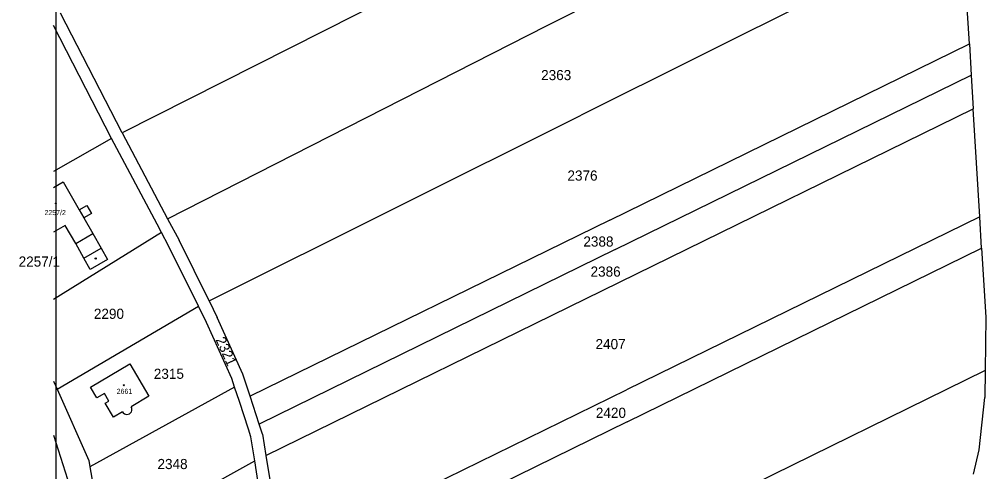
# Model space of a CAD drawing. Extents: x -565355 to -564154, y -1097649 to -1095548.
# Drawn here: x -565355.1 to -565030.7, y -1097072.9 to -1096921.2 of the extents above; entities that cross this region are included whole.
import ezdxf

# ---------------------------------------------------------------- set-up
doc = ezdxf.new("R2010")
doc.units = 0
for name, color, linetype in [('Vrstva 1', 7, 'Continuous'), ('Vrstva 18', 7, 'Continuous'), ('Vrstva 19', 7, 'Continuous'), ('Vrstva 25', 7, 'Continuous'), ('Vrstva 4', 7, 'Continuous'), ('Vrstva 63', 7, 'Continuous')]:
    doc.layers.add(name, color=color, linetype=linetype)

msp = doc.modelspace()

# ---------------------------------------------------------------- linework, layer by layer
at = {"layer": 'Vrstva 1'}
for p, q in [((-565178.1, -1096923.38), (-565050.85, -1096858.7)), ((-565191.34, -1096893.95), (-565320.5, -1096959.27)), ((-565041.65, -1096891.05), (-565166.5, -1096953.32)), ((-565036.11, -1096929.37), (-565037.8, -1096901.06)), ((-565320.5, -1096959.27), (-565341.23, -1096919.07)), ((-565324.11, -1096961.15), (-565343.59, -1096923.24)), ((-565305.34, -1096988.06), (-565178.1, -1096923.38)), ((-565156.86, -1096988.48), (-565036.11, -1096929.37)), ((-565036.11, -1096929.37), (-565035.5, -1096939.86)), ((-565155.02, -1096998.39), (-565035.5, -1096939.86)), ((-565035.5, -1096939.86), (-565034.85, -1096951.18)), ((-565153.57, -1097009.3), (-565034.85, -1096951.18)), ((-565032.66, -1096987.4), (-565034.85, -1096951.18)), ((-565291.35, -1097015.6), (-565166.5, -1096953.32)), ((-565324.11, -1096961.15), (-565343.59, -1096972.17)), ((-565308.84, -1096989.84), (-565324.11, -1096961.15)), ((-565320.5, -1096959.27), (-565305.34, -1096988.06)), ((-565343.59, -1096977.56), (-565340.37, -1096975.69)), ((-565340.37, -1096975.69), (-565334.99, -1096985.04)), ((-565334.99, -1096985.04), (-565332.43, -1096983.57)), ((-565332.43, -1096983.57), (-565330.88, -1096986.25)), ((-565330.88, -1096986.25), (-565333.44, -1096987.73)), ((-565333.44, -1096987.73), (-565330.43, -1096992.97)), ((-565305.34, -1096988.06), (-565301.41, -1096995.28)), ((-565032.66, -1096987.4), (-565151.18, -1097045.38)), ((-565032.02, -1096997.89), (-565032.66, -1096987.4)), ((-565339.67, -1096990.28), (-565343.59, -1096992.54)), ((-565336.13, -1096996.36), (-565339.67, -1096990.28)), ((-565307.31, -1096992.7), (-565308.84, -1096989.84)), ((-565156.86, -1096988.48), (-565277.62, -1097047.6)), ((-565307.31, -1096992.7), (-565343.59, -1097015.13)), ((-565330.43, -1096992.97), (-565327.61, -1096997.9)), ((-565304.96, -1096997.11), (-565307.31, -1096992.7)), ((-565333.4, -1097001.24), (-565336.13, -1096996.36)), ((-565327.61, -1096997.9), (-565325.43, -1097001.67)), ((-565294.97, -1097017.32), (-565304.96, -1096997.11)), ((-565291.35, -1097015.6), (-565301.41, -1096995.28)), ((-565150.98, -1097056.12), (-565032.02, -1096997.89)), ((-565032.02, -1096997.89), (-565030.65, -1097021.09)), ((-565155.02, -1096998.39), (-565274.54, -1097056.92)), ((-565331.28, -1097005.02), (-565333.4, -1097001.24)), ((-565325.43, -1097001.67), (-565331.28, -1097005.02)), ((-565272.29, -1097067.43), (-565153.57, -1097009.3)), ((-565342.42, -1097045.24), (-565294.97, -1097017.32)), ((-565292.22, -1097022.89), (-565294.97, -1097017.32)), ((-565291.35, -1097015.6), (-565288.6, -1097021.18)), ((-565283.77, -1097041.61), (-565292.22, -1097022.89)), ((-565280.04, -1097040.16), (-565288.6, -1097021.18)), ((-565030.65, -1097021.09), (-565030.82, -1097038.96)), ((-565331.16, -1097044.52), (-565317.95, -1097036.71)), ((-565317.95, -1097036.71), (-565311.55, -1097047.57)), ((-565030.82, -1097038.96), (-565149.44, -1097097.1)), ((-565030.82, -1097038.96), (-565030.9, -1097047.96)), ((-565343.59, -1097042.53), (-565342.42, -1097045.24)), ((-565282.82, -1097044.5), (-565283.77, -1097041.61)), ((-565277.62, -1097047.6), (-565280.04, -1097040.16)), ((-565342.42, -1097045.24), (-565331.74, -1097069.12)), ((-565282.82, -1097044.5), (-565331.38, -1097071.21)), ((-565329.03, -1097048.14), (-565331.16, -1097044.52)), ((-565281.2, -1097049.39), (-565282.82, -1097044.5)), ((-565269.7, -1097103.36), (-565151.18, -1097045.38)), ((-565326.5, -1097046.68), (-565329.03, -1097048.14)), ((-565325.01, -1097049.21), (-565326.5, -1097046.68)), ((-565326.22, -1097049.95), (-565325.01, -1097049.21)), ((-565311.55, -1097047.57), (-565317.54, -1097051.08)), ((-565278.14, -1097058.67), (-565281.2, -1097049.39)), ((-565274.54, -1097056.92), (-565277.62, -1097047.6)), ((-565032.89, -1097065.5), (-565030.9, -1097047.96)), ((-565323.47, -1097054.6), (-565326.22, -1097049.95)), ((-565320.42, -1097052.8), (-565323.47, -1097054.6)), ((-565150.98, -1097056.12), (-565269.93, -1097114.34)), ((-565277.31, -1097061.2), (-565278.14, -1097058.67)), ((-565273.41, -1097060.26), (-565274.54, -1097056.92)), ((-565343.59, -1097060.63), (-565336.41, -1097083.11)), ((-565276.02, -1097069.29), (-565277.31, -1097061.2)), ((-565273.41, -1097060.26), (-565272.29, -1097067.43)), ((-565034.69, -1097073.69), (-565032.89, -1097065.5)), ((-565331.74, -1097069.12), (-565331.38, -1097071.21)), ((-565272.29, -1097067.43), (-565269.38, -1097085.52)), ((-565331.38, -1097071.21), (-565330.38, -1097076.97)), ((-565327.99, -1097097.88), (-565276.02, -1097069.29)), ((-565273.39, -1097085.81), (-565276.02, -1097069.29))]:
    msp.add_line(p, q, dxfattribs=at)
msp.add_arc((-565318.94, -1097052.01), 1.68, 208.0808, 33.6124, dxfattribs=at)
at = {"layer": 'Vrstva 25'}
for centre in [(-565342.78, -1096982.89), (-565329.43, -1097001.38), (-565319.99, -1097043.89)]:
    msp.add_circle(centre, 0.175, dxfattribs=at)
at = {"layer": 'Vrstva 4'}
for p, q in [((-565334.99, -1096985.04), (-565333.44, -1096987.73)), ((-565336.13, -1096996.36), (-565330.43, -1096992.97)), ((-565333.4, -1097001.24), (-565327.61, -1096997.9))]:
    msp.add_line(p, q, dxfattribs=at)
at = {"layer": 'Vrstva 63'}
msp.add_line((-565342.77, -1095547.8), (-565342.77, -1097647.8), dxfattribs=at)

# ---------------------------------------------------------------- texts
at = {"layer": 'Vrstva 18'}
for s, p in [('2363', (-565179.89, -1096941.55)), ('2376', (-565171.06, -1096975.25)), ('2388', (-565165.71, -1096997.38)), ('2257/1', (-565355.3, -1097004.1)), ('2386', (-565163.3, -1097007.46)), ('2290', (-565330.04, -1097021.62)), ('2407', (-565161.63, -1097031.78)), ('2315', (-565309.92, -1097041.74)), ('2420', (-565161.52, -1097054.83)), ('2348', (-565308.69, -1097072.01))]:
    msp.add_text(s, height=3.4, dxfattribs=at).set_placement(p)
msp.add_text('2321', height=3.4, rotation=294.3, dxfattribs=at).set_placement((-565289.26, -1097028.58))
at = {"layer": 'Vrstva 19'}
for s, p in [('2257/2', (-565346.62, -1096986.82)), ('2661', (-565322.39, -1097046.77))]:
    msp.add_text(s, height=1.7, dxfattribs=at).set_placement(p)

doc.saveas('drawing.dxf')
